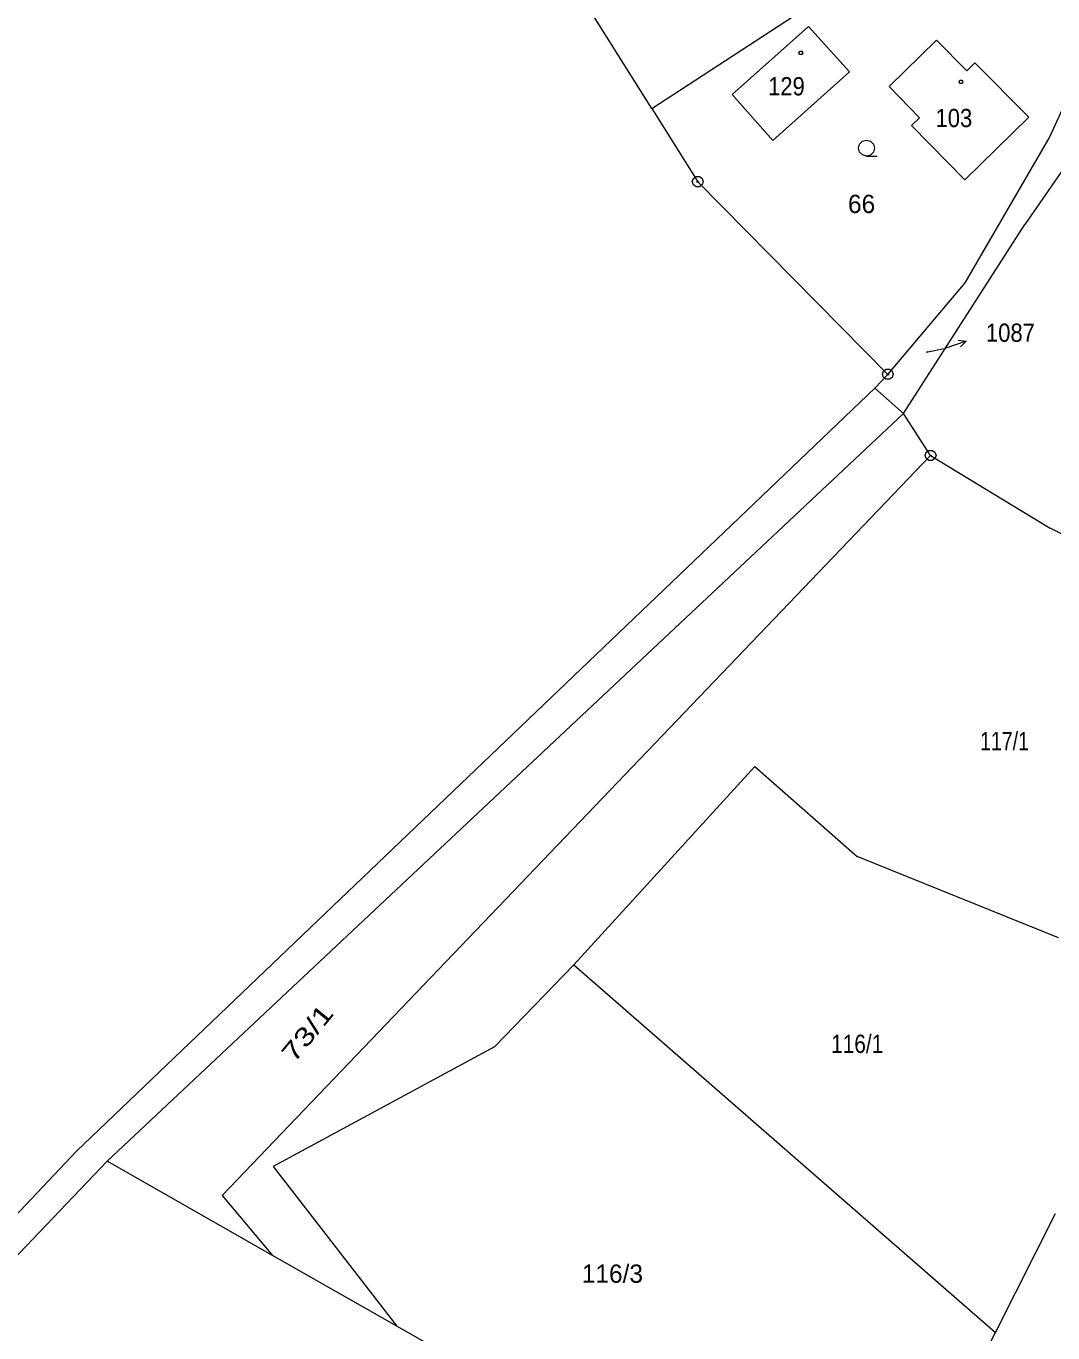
# Model space of a CAD drawing. Extents: x -687390 to -684106, y -954833 to -951648.
# Drawn here: x -687064.8 to -686969.4, y -952648.7 to -952527.1 of the extents above; entities that cross this region are included whole.
import ezdxf

# ---------------------------------------------------------------- set-up
doc = ezdxf.new("R2010")
doc.units = 0
doc.header["$LTSCALE"] = 0.68
for name, color, linetype, lineweight in [('1', 7, 'Continuous', 13), ('3', 7, 'Continuous', 13), ('5', 7, 'Continuous', 13), ('7', 7, 'Continuous', 13), ('8', 7, 'Continuous', 13)]:
    doc.layers.add(name, color=color, linetype=linetype, lineweight=lineweight)
doc.layers.add('2', color=7, linetype='Continuous')

msp = doc.modelspace()

# ---------------------------------------------------------------- linework, layer by layer
at = {"layer": '1'}
for p, q in [((-687006.67, -952534.81), (-686985.77, -952521.15)), ((-686977.37, -952531.3), (-686980.2, -952528.43)), ((-687006.67, -952534.81), (-687002.39, -952541.61)), ((-686965.86, -952536.72), (-686971.98, -952545.58)), ((-686984.71, -952559.53), (-686985.93, -952560.81)), ((-686985.93, -952560.81), (-687060.17, -952631.78)), ((-686983.25, -952563.16), (-686985.93, -952560.81)), ((-686980.74, -952567.08), (-687046.61, -952635.9)), ((-686980.74, -952567.08), (-686969.61, -952573.84)), ((-686957.31, -952579.96), (-686969.61, -952573.84)), ((-686997.1, -952596.02), (-686987.57, -952604.38)), ((-686968.84, -952611.94), (-686987.57, -952604.38)), ((-687013.93, -952614.44), (-686974.72, -952648.66)), ((-687089.87, -952663.24), (-687060.17, -952631.78)), ((-687041.88, -952633.21), (-687030.39, -952648.06)), ((-687046.61, -952635.9), (-687041.93, -952641.49)), ((-686974.72, -952648.66), (-686969.14, -952637.58)), ((-687003.19, -952663.54), (-687030.39, -952648.06))]:
    msp.add_line(p, q, dxfattribs=at)
for points in [[(-687006.67, -952534.81), (-687015.79, -952520.28), (-687022.1, -952513.92)], [(-687002.39, -952541.61), (-686984.71, -952559.53), (-686977.54, -952551.02), (-686969.71, -952537.55), (-686966.27, -952530.08), (-686966.24, -952522.04), (-686964.21, -952515.71)], [(-686977.37, -952531.3), (-686976.63, -952530.55), (-686971.62, -952535.61), (-686977.55, -952541.44), (-686982.52, -952536.38), (-686981.78, -952535.65), (-686984.61, -952532.76), (-686980.2, -952528.43)], [(-686980.74, -952567.08), (-686983.25, -952563.16), (-686971.98, -952545.58)], [(-687119.52, -952681.38), (-687116.32, -952682.25), (-687088.8, -952665.73), (-687057.31, -952632.73), (-686983.25, -952563.16)], [(-686997.1, -952596.02), (-687013.93, -952614.44), (-687021.29, -952622.09), (-687041.88, -952633.21)], [(-687030.39, -952648.06), (-687041.93, -952641.49), (-687057.31, -952632.73)], [(-686996.59, -952692.15), (-686983.91, -952666.94), (-686974.72, -952648.66)]]:
    msp.add_lwpolyline(points, dxfattribs=at)
msp.add_lwpolyline([(-686992.1, -952527.17), (-686988.3, -952531.39), (-686995.4, -952537.76), (-686999.18, -952533.51)], close=True, dxfattribs=at)
at = {"layer": '3'}
msp.add_lwpolyline([(-686986.69, -952539.22), (-686987.07, -952539.12), (-686987.34, -952538.85), (-686987.44, -952538.48), (-686987.34, -952538.11), (-686987.07, -952537.84), (-686986.7, -952537.74), (-686986.33, -952537.84), (-686986.06, -952538.11), (-686985.96, -952538.49), (-686986.06, -952538.87), (-686986.33, -952539.14), (-686986.71, -952539.24), (-686985.71, -952539.24)], dxfattribs=at)
at = {"layer": '5'}
for points in [[(-686992.72, -952529.47), (-686992.63, -952529.62), (-686992.72, -952529.77), (-686992.9, -952529.77), (-686992.99, -952529.62), (-686992.9, -952529.47)], [(-686977.83, -952532.16), (-686977.74, -952532.31), (-686977.83, -952532.46), (-686978.01, -952532.46), (-686978.1, -952532.31), (-686978.01, -952532.16)]]:
    msp.add_lwpolyline(points, close=True, dxfattribs=at)
at = {"layer": '7'}
for p in [(-686981.17, -952557.46), (-686977.434, -952556.432)]:
    msp.add_line(p, (-686979.33, -952557.1), dxfattribs=at)
msp.add_lwpolyline([(-686978.177, -952556.339), (-686977.434, -952556.432), (-686977.955, -952556.971)], dxfattribs=at)
at = {"layer": '8'}
for p, q in [((-687002.51, -952541.61), (-687002.27, -952541.61)), ((-686984.83, -952559.53), (-686984.59, -952559.53)), ((-686980.86, -952567.08), (-686980.62, -952567.08))]:
    msp.add_line(p, q, dxfattribs=at)
for points in [[(-687002.24, -952541.13), (-687001.99, -952541.31), (-687001.89, -952541.6), (-687001.99, -952541.89), (-687002.24, -952542.07), (-687002.55, -952542.07), (-687002.8, -952541.89), (-687002.9, -952541.6), (-687002.8, -952541.31), (-687002.55, -952541.13)], [(-686984.56, -952559.05), (-686984.31, -952559.23), (-686984.21, -952559.52), (-686984.31, -952559.81), (-686984.56, -952559.99), (-686984.87, -952559.99), (-686985.12, -952559.81), (-686985.22, -952559.52), (-686985.12, -952559.23), (-686984.87, -952559.05)], [(-686980.59, -952566.6), (-686980.34, -952566.78), (-686980.24, -952567.07), (-686980.34, -952567.36), (-686980.59, -952567.54), (-686980.9, -952567.54), (-686981.15, -952567.36), (-686981.25, -952567.07), (-686981.15, -952566.78), (-686980.9, -952566.6)]]:
    msp.add_lwpolyline(points, close=True, dxfattribs=at)

# ---------------------------------------------------------------- texts
at = {"layer": '2'}
for s, height, width, p in [('129', 1.7, 0.9, (-686995.855, -952533.58)), ('103', 1.7, 0.9, (-686980.285, -952536.53)), ('1087', 0.1, 0.9, (-686981.124, -952557.46)), ('117/1', 1.7, 0.8, (-686976.145, -952594.49)), ('116/1', 1.7, 0.85, (-686989.985, -952622.65))]:
    msp.add_text(s, height=height, dxfattribs=dict(at, width=width)).set_placement(p)
for s, p in [('66', (-686988.426, -952544.52)), ('116/3', (-687013.175, -952644.03))]:
    msp.add_text(s, height=1.7, dxfattribs=at).set_placement(p)
at = {"layer": '2', "width": 1.35}
msp.add_text('73/1', height=1.7, rotation=50.879, dxfattribs=at).set_placement((-687039.92, -952623.652))
at = {"layer": '7', "width": 0.9}
msp.add_text('1087', height=1.7, dxfattribs=at).set_placement((-686975.595, -952556.5))

doc.saveas('drawing.dxf')
